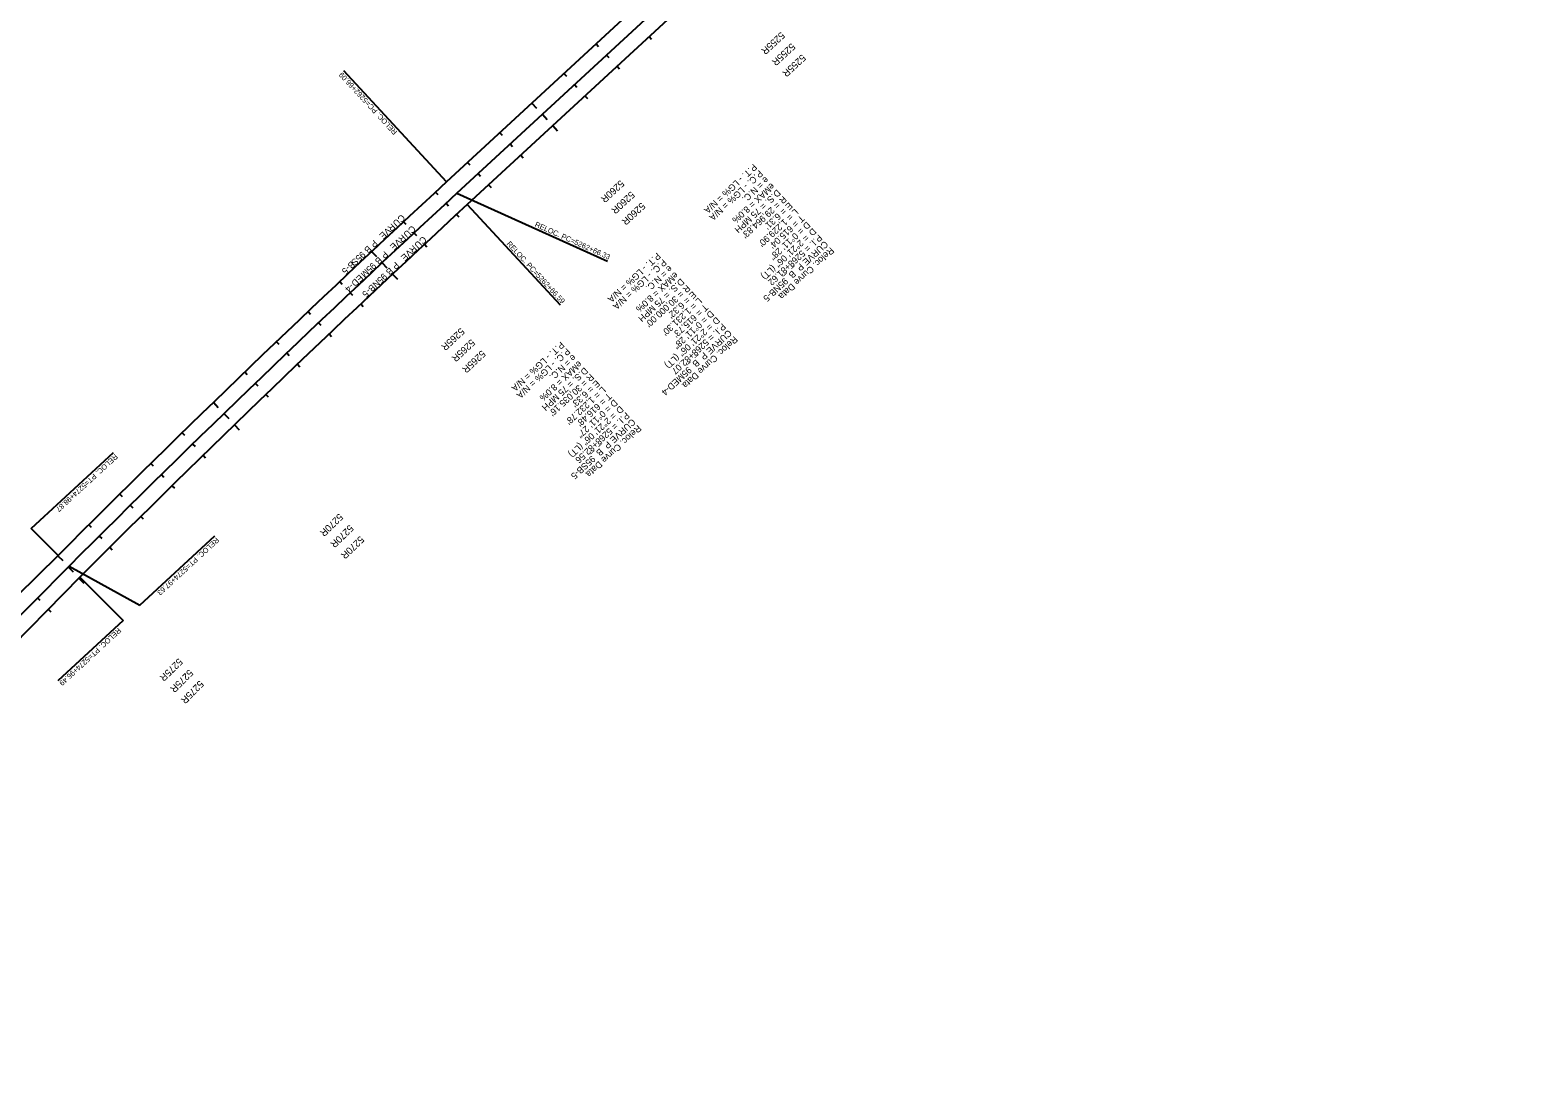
# Model space of a CAD drawing. Extents: x 2161211 to 2175594, y 601812 to 617732.
# Drawn here: x 2164514 to 2167964, y 605580 to 607997 of the extents above; entities that cross this region are included whole.
import ezdxf

# ---------------------------------------------------------------- set-up
doc = ezdxf.new("R2010")
doc.units = 0
for name, color, linetype in [('RD_HC_CL_Rel', 7, 'Continuous'), ('RD_HC_Data_Rel', 7, 'Continuous'), ('RD_HC_Data_Tic_Rel', 7, 'Continuous'), ('RD_HC_TX_Rel_Sta50', 7, 'Continuous')]:
    doc.layers.add(name, color=color, linetype=linetype)

msp = doc.modelspace()

# ---------------------------------------------------------------- linework, layer by layer
at = {"layer": 'RD_HC_CL_Rel'}
for p, q in [((2167916, 609910.7), (2165466.8, 607649.1)), ((2167939.8, 609884.8), (2165490.6, 607623.3)), ((2167963.7, 609859.1), (2165514.5, 607597.4)), ((2164578.5, 606794.4), (2163416.7, 605647.9)), ((2164603.4, 606769.6), (2163450.6, 605614)), ((2164628.3, 606744.8), (2163484.6, 605580.1))]:
    msp.add_line(p, q, dxfattribs=at)
for radius, start in [(30035.2, 132.71939), (30000, 132.71947), (29964.8, 132.71939)]:
    msp.add_arc((2185842.9, 585582.7), radius, start, 135.07107, dxfattribs=at)
at = {"layer": 'RD_HC_Data_Rel'}
for p, q in [((2165466.8, 607649.1), (2165232.2, 607903.1)), ((2165490.6, 607623.3), (2165835.2, 607467.8)), ((2165514.5, 607597.4), (2165726.7, 607367.7)), ((2164516.8, 606856), (2164705.5, 607030.2)), ((2164578.5, 606794.4), (2164516.8, 606856)), ((2164765.1, 606680.2), (2164937.3, 606839.3)), ((2164603.4, 606769.6), (2164765.1, 606680.2)), ((2164628.3, 606744.8), (2164727.6, 606645.6)), ((2164727.6, 606645.6), (2164577.7, 606507.2))]:
    msp.add_line(p, q, dxfattribs=at)
at = {"layer": 'RD_HC_Data_Tic_Rel'}
for p, q in [((2165930.7, 607981.8), (2165936.2, 607975.9)), ((2165809.2, 607965.3), (2165814.6, 607959.4)), ((2165833.2, 607939.6), (2165838.6, 607933.7)), ((2165735.7, 607897.5), (2165741.2, 607891.6)), ((2165857.3, 607914), (2165862.7, 607908.1)), ((2165759.7, 607871.8), (2165765.2, 607865.9)), ((2165662.3, 607829.6), (2165673.1, 607817.9)), ((2165783.8, 607846.1), (2165789.2, 607840.3)), ((2165686.3, 607803.9), (2165697.1, 607792.2)), ((2165588.8, 607761.8), (2165594.2, 607755.9)), ((2165710.3, 607778.3), (2165721.2, 607766.5)), ((2165612.8, 607736.1), (2165618.2, 607730.2)), ((2165515.3, 607693.9), (2165520.7, 607688.1)), ((2165636.9, 607710.5), (2165642.3, 607704.6)), ((2165539.3, 607668.3), (2165544.8, 607662.4)), ((2165441.9, 607626.1), (2165447.3, 607620.2)), ((2165563.4, 607642.6), (2165568.8, 607636.7)), ((2165465.9, 607600.4), (2165471.3, 607594.5)), ((2165368.6, 607558), (2165374, 607552.2)), ((2165489.9, 607574.8), (2165495.4, 607568.9)), ((2165392.6, 607532.4), (2165398, 607526.5)), ((2165295.5, 607489.8), (2165306.5, 607478.1)), ((2165416.7, 607506.7), (2165422.1, 607500.9)), ((2165319.5, 607464.1), (2165330.5, 607452.4)), ((2165222.7, 607421.2), (2165228.2, 607415.4)), ((2165343.6, 607438.4), (2165354.6, 607426.8)), ((2165246.7, 607395.5), (2165252.2, 607389.7)), ((2165150.1, 607352.5), (2165155.6, 607346.7)), ((2165270.8, 607369.9), (2165276.3, 607364.1)), ((2165174.1, 607326.8), (2165179.6, 607321)), ((2165077.7, 607283.4), (2165083.3, 607277.7)), ((2165198.2, 607301.1), (2165203.7, 607295.3)), ((2165101.8, 607257.7), (2165107.3, 607252)), ((2165005.6, 607214.2), (2165011.2, 607208.4)), ((2165125.8, 607232.1), (2165131.4, 607226.3)), ((2165029.6, 607188.5), (2165035.2, 607182.7)), ((2164933.7, 607144.7), (2164944.8, 607133.2)), ((2165053.7, 607162.8), (2165059.3, 607157.1)), ((2164957.7, 607119), (2164968.9, 607107.5)), ((2164862, 607074.9), (2164867.6, 607069.2)), ((2164981.8, 607093.3), (2164992.9, 607081.9)), ((2164886, 607049.2), (2164891.6, 607043.5)), ((2164790.6, 607005), (2164796.2, 606999.3)), ((2164910.1, 607023.6), (2164915.7, 607017.9)), ((2164814.6, 606979.3), (2164820.2, 606973.6)), ((2164719.4, 606934.8), (2164725, 606929.1)), ((2164838.7, 606953.6), (2164844.3, 606947.9)), ((2164743.4, 606909.1), (2164749, 606903.4)), ((2164648.4, 606864.3), (2164654.1, 606858.6)), ((2164767.5, 606883.4), (2164773.1, 606877.7)), ((2164672.4, 606838.6), (2164678.1, 606832.9)), ((2164577.7, 606793.6), (2164588.9, 606782.3)), ((2164696.5, 606813), (2164702.2, 606807.3)), ((2164601.7, 606767.9), (2164613, 606756.6)), ((2164625.8, 606742.3), (2164637.2, 606731)), ((2164531.1, 606697.1), (2164536.7, 606691.5)), ((2164555.7, 606670.9), (2164561.5, 606665.3))]:
    msp.add_line(p, q, dxfattribs=at)

# ---------------------------------------------------------------- texts
at = {"layer": 'RD_HC_Data_Rel'}
for s, height, rotation, p in [('RELOC. PC=5262+66.09', 12, 132.7194, (2165355.3, 607764)), ('P.T. - LG% = N/A', 15, 222.7195, (2166169, 607691.7)), ('P.C. - LG% = N/A', 15, 222.7195, (2166182.5, 607677)), ('e = N.C.', 15, 222.7195, (2166196.1, 607662.3)), ('eMAX = 8.0%', 15, 222.7195, (2166209.7, 607647.7)), ('D.S. = 75 MPH', 15, 222.7195, (2166223.2, 607633)), ("R = 29,964.83'", 15, 222.7195, (2166236.8, 607618.3)), ("L = 1,229.90'", 15, 222.7195, (2166263.9, 607588.9)), ("E = 6.31'", 15, 222.7195, (2166250.4, 607603.6)), ('R', 15, 223.0305, (2165341.4, 607555.2)), ('U', 15, 223.0001, (2165353, 607566.1)), ('C', 15, 222.9721, (2165363.8, 607576.1)), ('RELOC. PC=5262+66.33', 12, 335.725, (2165667.8, 607547.7)), ("T = 615.04'", 15, 222.7195, (2166277.5, 607574.2)), ('D = 0°11\' 28"', 15, 222.7195, (2166291.1, 607559.5)), ('E', 15, 223.0818, (2165321.7, 607536.9)), ('V', 15, 223.0561, (2165331.5, 607546.1)), ('R', 15, 223.0296, (2165365.7, 607529.9)), ('U', 15, 222.9992, (2165377.4, 607540.7)), ('C', 15, 222.9711, (2165388.1, 607550.7)), ('C', 15, 222.9681, (2165413.2, 607526.1)), ('    = 2°21\' 06" (LT)', 15, 222.7195, (2166304.6, 607544.8)), ('P.I. = 5268+81.62', 15, 222.7195, (2166318.2, 607530.1)), ('D', 15, 222.7195, (2166304.6, 607544.8)), ('9', 15, 223.2085, (2165273.2, 607491.4)), ('B', 15, 223.1723, (2165287, 607504.4)), ('P', 15, 223.1361, (2165300.9, 607517.4)), ('P', 15, 223.1354, (2165325.2, 607492)), ('E', 15, 223.081, (2165346, 607511.5)), ('V', 15, 223.0553, (2165355.9, 607520.7)), ('E', 15, 223.0781, (2165371.1, 607486.8)), ('V', 15, 223.0524, (2165381, 607496)), ('R', 15, 223.0267, (2165390.8, 607505.2)), ('U', 15, 222.9962, (2165402.5, 607516)), ('RELOC. PC=5262+66.59', 12, 312.7194, (2165603.6, 607506.8)), ('P.T. - LG% = N/A', 15, 222.7195, (2165948.6, 607488.2)), ('CURVE P_B_95NB-5', 15, 222.7195, (2166331.8, 607515.4)), ('Reloc. Curve Data', 15, 222.7195, (2166345.4, 607500.7)), ('5', 15, 223.3112, (2165234, 607454.5)), ('-', 15, 223.2972, (2165239.3, 607459.6)), ('B', 15, 223.2715, (2165249.1, 607468.8)), ('S', 15, 223.2505, (2165257.1, 607476.3)), ('5', 15, 223.2295, (2165265.2, 607483.9)), ('M', 15, 223.2499, (2165281.5, 607450.9)), ('5', 15, 223.2289, (2165289.5, 607458.5)), ('9', 15, 223.2078, (2165297.5, 607466)), ('B', 15, 223.1716, (2165311.4, 607479)), ('B', 15, 223.1688, (2165336.5, 607454.4)), ('P', 15, 223.1326, (2165350.3, 607467.3)), ('P.C. - LG% = N/A', 15, 222.7195, (2165962.1, 607473.5)), ('e = N.C.', 15, 222.7195, (2165975.7, 607458.8)), ('-', 15, 223.3411, (2165246.7, 607418.2)), ('D', 15, 223.3107, (2165258.3, 607429.1)), ('E', 15, 223.285, (2165268.1, 607438.4)), ('B', 15, 223.2754, (2165295.9, 607416.2)), ('N', 15, 223.2472, (2165306.6, 607426.3)), ('5', 15, 223.2262, (2165314.6, 607433.8)), ('9', 15, 223.2051, (2165322.6, 607441.4)), ('eMAX = 8.0%', 15, 222.7195, (2165989.3, 607444.1)), ('D.S. = 75 MPH', 15, 222.7195, (2166002.8, 607429.4)), ('4', 15, 223.3551, (2165241.4, 607413.2)), ('5', 15, 223.3151, (2165280.7, 607401.9)), ('-', 15, 223.3011, (2165286.1, 607407)), ("R = 30,000.00'", 15, 222.7195, (2166016.4, 607414.7)), ("L = 1,231.30'", 15, 222.7195, (2166043.5, 607385.4)), ("E = 6.32'", 15, 222.7195, (2166030, 607400)), ("T = 615.73'", 15, 222.7195, (2166057.1, 607370.7)), ('D = 0°11\' 28"', 15, 222.7195, (2166070.7, 607356)), ('    = 2°21\' 06" (LT)', 15, 222.7195, (2166084.2, 607341.3)), ('P.I. = 5268+82.07', 15, 222.7195, (2166097.8, 607326.6)), ('D', 15, 222.7195, (2166084.2, 607341.3)), ('P.T. - LG% = N/A', 15, 222.7195, (2165728.2, 607284.7)), ('CURVE P_B_95MED-4', 15, 222.7195, (2166111.4, 607311.9)), ('Reloc. Curve Data', 15, 222.7195, (2166124.9, 607297.2)), ('P.C. - LG% = N/A', 15, 222.7195, (2165741.7, 607270)), ('e = N.C.', 15, 222.7195, (2165755.3, 607255.3)), ('eMAX = 8.0%', 15, 222.7195, (2165768.9, 607240.6)), ('D.S. = 75 MPH', 15, 222.7195, (2165782.4, 607225.9)), ("R = 30,035.16'", 15, 222.7195, (2165796, 607211.2)), ("L = 1,232.78'", 15, 222.7195, (2165823.1, 607181.8)), ("E = 6.33'", 15, 222.7195, (2165809.6, 607196.5)), ("T = 616.48'", 15, 222.7195, (2165836.7, 607167.1)), ('D = 0°11\' 27"', 15, 222.7195, (2165850.3, 607152.4)), ('    = 2°21\' 06" (LT)', 15, 222.7195, (2165863.8, 607137.7)), ('CURVE P_B_95SB-5', 15, 222.7195, (2165891, 607108.4)), ('P.I. = 5268+82.56', 15, 222.7195, (2165877.4, 607123.1)), ('D', 15, 222.7195, (2165863.8, 607137.7)), ('Reloc. Curve Data', 15, 222.7195, (2165904.5, 607093.7)), ('RELOC. PT=5274+98.87', 12, 222.7195, (2164708.2, 607027.3)), ('RELOC. PT=5274+97.63', 12, 222.7195, (2164940, 606836.3)), ('RELOC. PT=5274+96.49', 12, 222.7195, (2164715.9, 606629.4))]:
    msp.add_text(s, height=height, rotation=rotation, dxfattribs=at).set_placement(p)
at = {"layer": 'RD_HC_TX_Rel_Sta50'}
for s, rotation, p in [('5255R', 222.7194, (2166232, 607993.7)), ('5255R', 222.7195, (2166256, 607968)), ('5255R', 222.7194, (2166280.1, 607942.4)), ('5260R', 222.7194, (2165864.7, 607654.5)), ('5260R', 222.7195, (2165888.7, 607628.8)), ('5260R', 222.7194, (2165912.8, 607603.2)), ('5265R', 223.1656, (2165499.3, 607316.2)), ('5265R', 223.1657, (2165523.3, 607290.5)), ('5265R', 223.1657, (2165547.4, 607264.9)), ('5270R', 224.1194, (2165221.1, 606891.3)), ('5270R', 224.1207, (2165245.1, 606865.6)), ('5270R', 224.1217, (2165269.2, 606839.9)), ('5275R', 224.6205, (2164854, 606560.1)), ('5275R', 225.0711, (2164878, 606534.6)), ('5275R', 225.5215, (2164902, 606509.2))]:
    msp.add_text(s, height=16, rotation=rotation, dxfattribs=at).set_placement(p)

doc.saveas('drawing.dxf')
